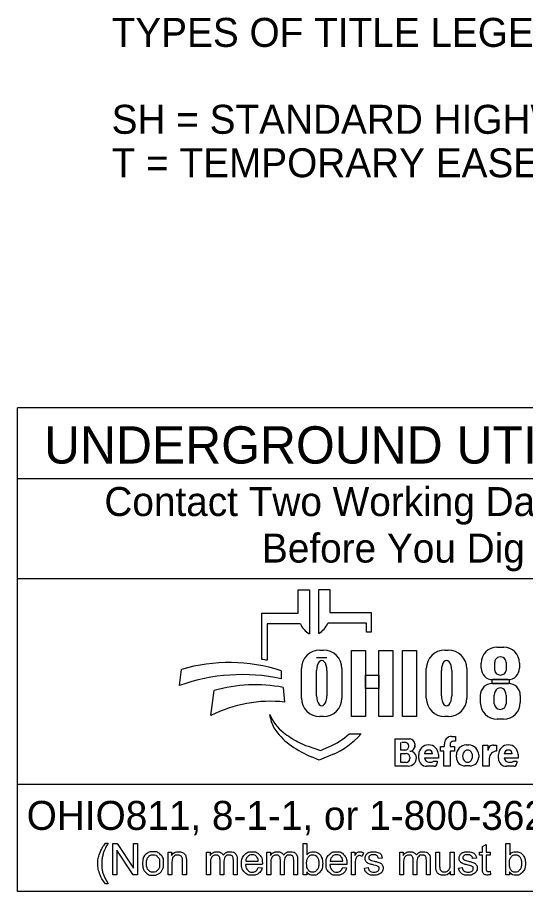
# Model space of a CAD drawing. Extents: x 0 to 34, y 0 to 22.
# Drawn here: x 18.411 to 20.865, y 5.128 to 9.351 of the extents above; entities that cross this region are included whole.
import ezdxf

# ---------------------------------------------------------------- set-up
doc = ezdxf.new("R2010")
doc.units = 0
doc.layers.add('SH_Data', color=7, linetype='Continuous')
doc.layers.add('SH_Text', color=7, linetype='Continuous')

msp = doc.modelspace()

# ---------------------------------------------------------------- linework, layer by layer
at = {"layer": 'SH_Data'}
for p, q in [((18.4115, 5.1281), (18.4115, 7.4656)), ((22.6615, 7.4656), (18.4115, 7.4656)), ((18.4115, 7.124), (22.6615, 7.124)), ((18.4115, 6.6407), (22.6615, 6.6407)), ((22.6615, 5.646), (18.4115, 5.646)), ((22.6615, 5.1281), (18.4115, 5.1281))]:
    msp.add_line(p, q, dxfattribs=at)
at = {"layer": 'SH_Text'}
for p, q in [((19.7675, 6.4736), (19.7675, 6.5851)), ((19.7675, 6.5851), (19.8211, 6.5851)), ((19.8211, 6.5851), (19.8211, 6.373)), ((19.8668, 6.3754), (19.8668, 6.5874)), ((19.8668, 6.5874), (19.9205, 6.5874)), ((19.9205, 6.5874), (19.9205, 6.4759)), ((19.5915, 6.2497), (19.5915, 6.4736)), ((19.5915, 6.4736), (19.7675, 6.4736)), ((19.9205, 6.4759), (20.1197, 6.4759)), ((20.1197, 6.4759), (20.1197, 6.3821)), ((19.6168, 6.4222), (19.6168, 6.2453)), ((19.7779, 6.4222), (19.6168, 6.4222)), ((20.0964, 6.4245), (19.91, 6.4245)), ((20.0964, 6.3821), (20.0964, 6.4245)), ((20.1197, 6.3821), (20.0964, 6.3821)), ((19.8725, 6.2944), (19.889, 6.2944)), ((20.4755, 6.2944), (20.4921, 6.2944)), ((20.7271, 6.3084), (20.7598, 6.3084)), ((19.9058, 6.2574), (19.856, 6.2574)), ((20.6508, 6.2078), (20.6508, 6.2321)), ((20.7169, 6.1964), (20.7169, 6.2357)), ((20.7711, 6.2357), (20.7711, 6.1964)), ((20.8361, 6.2321), (20.8361, 6.2078)), ((19.1942, 6.1234), (19.2036, 6.2016)), ((19.6849, 6.1951), (19.6849, 6.1562)), ((19.783, 6.063), (19.783, 6.205)), ((19.8559, 6.0743), (19.8559, 6.1967)), ((19.9057, 6.1967), (19.9057, 6.0743)), ((19.9785, 6.205), (19.9785, 6.063)), ((20.3861, 6.063), (20.3861, 6.205)), ((20.459, 6.0743), (20.459, 6.1967)), ((20.5088, 6.1967), (20.5088, 6.0743)), ((20.5815, 6.205), (20.5815, 6.063)), ((20.7049, 6.1335), (20.7823, 6.1335)), ((20.7801, 6.1518), (20.7068, 6.1518)), ((19.346, 5.9789), (19.3607, 6.099)), ((19.6948, 6.1145), (19.701, 6.0435)), ((20.6471, 6.0416), (20.6471, 6.0756)), ((20.7146, 6.0356), (20.7146, 6.0766)), ((20.7714, 6.0766), (20.7714, 6.0356)), ((20.8402, 6.0756), (20.8402, 6.0416)), ((19.6337, 5.966), (19.6306, 5.9839)), ((19.889, 5.9735), (19.8725, 5.9735)), ((20.4921, 5.9735), (20.4755, 5.9735)), ((20.7592, 5.9607), (20.728, 5.9607)), ((20.014, 5.8901), (20.0714, 5.8901)), ((20.5079, 5.8779), (20.5273, 5.8779)), ((20.5273, 5.8779), (20.5273, 5.8549)), ((19.8156, 5.8297), (19.875, 5.8093)), ((20.2353, 5.7344), (20.2353, 5.8651)), ((20.2353, 5.8651), (20.3065, 5.8651)), ((20.2633, 5.8116), (20.2633, 5.8485)), ((20.2885, 5.8485), (20.2672, 5.8485)), ((20.3302, 5.8413), (20.3302, 5.8334)), ((20.4553, 5.8065), (20.4553, 5.8295)), ((20.4553, 5.8295), (20.4746, 5.8295)), ((20.4746, 5.8295), (20.4746, 5.84)), ((20.5007, 5.8379), (20.5007, 5.8295)), ((20.5007, 5.8295), (20.5222, 5.8295)), ((20.5273, 5.8544), (20.5172, 5.8544)), ((20.5222, 5.8295), (20.5222, 5.8065)), ((20.5791, 5.8361), (20.5912, 5.8361)), ((20.6593, 5.7332), (20.6593, 5.8359)), ((20.6593, 5.8359), (20.6839, 5.8359)), ((20.6839, 5.8359), (20.6839, 5.809)), ((20.7111, 5.8359), (20.725, 5.8359)), ((20.725, 5.8359), (20.725, 5.8062)), ((19.9322, 5.7897), (19.869, 5.7622)), ((19.875, 5.8093), (19.916, 5.8271)), ((20.2827, 5.8116), (20.2633, 5.8116)), ((20.2633, 5.7522), (20.2633, 5.7951)), ((20.2633, 5.7951), (20.2888, 5.7951)), ((20.3498, 5.7711), (20.3498, 5.7896)), ((20.4164, 5.7935), (20.3779, 5.7935)), ((20.4444, 5.7896), (20.4444, 5.7719)), ((20.4702, 5.8065), (20.4553, 5.8065)), ((20.4702, 5.7332), (20.4702, 5.8065)), ((20.5222, 5.8065), (20.5007, 5.8065)), ((20.5007, 5.8065), (20.5007, 5.7332)), ((20.5313, 5.7775), (20.5313, 5.7883)), ((20.639, 5.7883), (20.639, 5.7775)), ((20.7348, 5.7711), (20.7348, 5.7896)), ((20.8013, 5.7935), (20.7628, 5.7935)), ((20.8293, 5.7896), (20.8293, 5.7719)), ((19.869, 5.7622), (19.8316, 5.7787)), ((20.2885, 5.7522), (20.2633, 5.7522)), ((20.3069, 5.7769), (20.3069, 5.7706)), ((20.3383, 5.774), (20.3383, 5.7737)), ((20.4444, 5.7719), (20.3779, 5.7719)), ((20.3989, 5.7526), (20.413, 5.7526)), ((20.4216, 5.7582), (20.4384, 5.7582)), ((20.4384, 5.7582), (20.4384, 5.7484)), ((20.6899, 5.7713), (20.6899, 5.7332)), ((20.8293, 5.7719), (20.7629, 5.7719)), ((20.7838, 5.7526), (20.7979, 5.7526)), ((20.8065, 5.7582), (20.8233, 5.7582)), ((20.8233, 5.7582), (20.8233, 5.7484)), ((20.2989, 5.7344), (20.2353, 5.7344)), ((20.4232, 5.7332), (20.3878, 5.7332)), ((20.5007, 5.7332), (20.4702, 5.7332)), ((20.5963, 5.7347), (20.5741, 5.7347)), ((20.6899, 5.7332), (20.6593, 5.7332)), ((20.8081, 5.7332), (20.7727, 5.7332))]:
    msp.add_line(p, q, dxfattribs=at)
for points in [[(20.0249, 6.2934), (20.0929, 6.2934), (20.0929, 5.9734), (20.0249, 5.9734)], [(20.1571, 6.2934), (20.225, 6.2934), (20.225, 5.9734), (20.1571, 5.9734)], [(20.2704, 6.2934), (20.3392, 6.2934), (20.3392, 5.9734), (20.2704, 5.9734)], [(20.0929, 6.1735), (20.1571, 6.1735), (20.1571, 6.1095), (20.0929, 6.1095)], [(20.7046, 6.1519), (20.7863, 6.1519), (20.7863, 6.1334), (20.7046, 6.1334)]]:
    msp.add_lwpolyline(points, close=True, dxfattribs=at)
for points in [[(18.8361, 5.3619), (18.8493, 5.3619)], [(18.8728, 5.2092), (18.8728, 5.3594), (18.8932, 5.3594), (18.9722, 5.2415), (18.9722, 5.3594), (18.9912, 5.3594), (18.9912, 5.2092), (18.9708, 5.2092), (18.8918, 5.3272), (18.8918, 5.2092), (18.8728, 5.2092)], [(19.8083, 5.2092), (19.7912, 5.2092), (19.7912, 5.3594), (19.8097, 5.3594), (19.8097, 5.3059)], [(20.6572, 5.2411), (20.6572, 5.3038), (20.6436, 5.3038), (20.6436, 5.3181), (20.6572, 5.3181), (20.6572, 5.345), (20.6757, 5.3561), (20.6757, 5.3181), (20.6941, 5.3181), (20.6941, 5.3038), (20.6757, 5.3038), (20.6757, 5.24)], [(20.7874, 5.2092), (20.7703, 5.2092), (20.7703, 5.3594), (20.7887, 5.3594), (20.7887, 5.3059)], [(19.1388, 5.2092), (19.1388, 5.3181), (19.1554, 5.3181), (19.1554, 5.3026)], [(19.3252, 5.2092), (19.3252, 5.3181), (19.3417, 5.3181), (19.3417, 5.3027)], [(19.4083, 5.2724), (19.4083, 5.2092), (19.3899, 5.2092), (19.3899, 5.2799)], [(19.4727, 5.2839), (19.4727, 5.2092), (19.4543, 5.2092), (19.4543, 5.2777)], [(19.6166, 5.2092), (19.6166, 5.3181), (19.6331, 5.3181), (19.6331, 5.3027)], [(19.6997, 5.2724), (19.6997, 5.2092), (19.6812, 5.2092), (19.6812, 5.2799)], [(19.7641, 5.2839), (19.7641, 5.2092), (19.7457, 5.2092), (19.7457, 5.2777)], [(20.0244, 5.2092), (20.0244, 5.3181), (20.041, 5.3181), (20.041, 5.3016)], [(20.0834, 5.3146), (20.077, 5.2975)], [(20.1734, 5.2899), (20.1553, 5.2875)], [(20.2576, 5.2092), (20.2576, 5.3181), (20.2741, 5.3181), (20.2741, 5.3027)], [(20.3407, 5.2724), (20.3407, 5.2092), (20.3222, 5.2092), (20.3222, 5.2799)], [(20.4051, 5.2839), (20.4051, 5.2092), (20.3867, 5.2092), (20.3867, 5.2777)], [(20.4319, 5.2507), (20.4319, 5.3181), (20.4503, 5.3181), (20.4503, 5.2578)], [(20.5016, 5.2598), (20.5016, 5.3181), (20.52, 5.3181), (20.52, 5.2092), (20.5035, 5.2092)], [(20.6279, 5.2899), (20.6099, 5.2875)], [(19.1572, 5.2686), (19.1572, 5.2092), (19.1388, 5.2092)], [(19.2272, 5.2761), (19.2272, 5.2092), (19.2087, 5.2092), (19.2087, 5.2754)], [(19.3436, 5.2657), (19.3436, 5.2092), (19.3252, 5.2092)], [(19.594, 5.2589), (19.5128, 5.2589)], [(19.5138, 5.274), (19.5746, 5.274)], [(19.5744, 5.2444), (19.5934, 5.242)], [(19.635, 5.2657), (19.635, 5.2092), (19.6166, 5.2092)], [(20.002, 5.2589), (19.9208, 5.2589)], [(19.9218, 5.274), (19.9826, 5.274)], [(19.9824, 5.2444), (20.0014, 5.242)], [(20.0428, 5.2662), (20.0428, 5.2092), (20.0244, 5.2092)], [(20.087, 5.2417), (20.1052, 5.2446)], [(20.276, 5.2657), (20.276, 5.2092), (20.2576, 5.2092)], [(20.5415, 5.2417), (20.5597, 5.2446)], [(19.8083, 5.2229), (19.8083, 5.2092)], [(20.5035, 5.2092), (20.5035, 5.2253)], [(20.6941, 5.2257), (20.6967, 5.2094)], [(20.7874, 5.2229), (20.7874, 5.2092)], [(18.8493, 5.1651), (18.8361, 5.1651)]]:
    msp.add_lwpolyline(points, dxfattribs=at)
for centre, radius, start, end in [((19.8693, 6.4589), 0.0985, 201.9296, 240.7469), ((19.8187, 6.4613), 0.0985, 299.2531, 338.0704), ((19.8725, 6.205), 0.0895, 90, 180), ((19.889, 6.205), 0.0895, 0, 90), ((20.4755, 6.205), 0.0895, 90, 180), ((20.4921, 6.205), 0.0895, 0, 90), ((20.7271, 6.2321), 0.0763, 90, 180), ((20.7598, 6.2321), 0.0763, 0, 90), ((19.4337, 5.4155), 0.8191, 72.1402, 106.3144), ((19.4634, 5.4408), 0.8191, 79.2074, 81.0007), ((19.4967, 5.2844), 0.8919, 77.8238, 109.8274), ((20.7068, 6.2078), 0.056, 180, 270), ((20.7801, 6.2078), 0.056, 270, 0), ((19.5606, 5.3947), 0.7322, 79.44, 105.8467), ((20.7049, 6.0756), 0.0579, 90, 180), ((20.7823, 6.0756), 0.0579, 0, 90), ((19.6327, 5.4115), 0.6357, 83.8248, 116.8021), ((19.8725, 6.063), 0.0895, 180, 270), ((19.889, 6.063), 0.0895, 270, 0), ((20.4755, 6.063), 0.0895, 180, 270), ((20.4921, 6.063), 0.0895, 270, 0), ((20.728, 6.0416), 0.081, 180, 270), ((20.7592, 6.0416), 0.081, 270, 0), ((19.818, 6.056), 0.2008, 201.0457, 232.5314), ((19.775, 5.9901), 0.1433, 189.6817, 216.0884), ((19.9087, 6.0875), 0.3088, 216.0884, 235.7167), ((20.0106, 6.3072), 0.5173, 232.5314, 241.794), ((19.7726, 6.1575), 0.3602, 293.4582, 312.0712), ((19.7726, 6.1575), 0.401, 293.4582, 317.8286), ((20.5079, 5.8443), 0.0335, 90, 187.5187), ((20.0752, 6.3318), 0.6044, 235.7167, 246.2325), ((19.9254, 6.1484), 0.3371, 241.794, 250.9821), ((20.2827, 5.8303), 0.0187, 270, 2.0582), ((20.2845, 5.8317), 0.0169, 357.8325, 90), ((20.3061, 5.8306), 0.0243, 270, 6.6529), ((20.3065, 5.8413), 0.0238, 0, 90), ((20.3167, 5.8291), 0.0175, 347.4023, 0), ((20.3971, 5.7896), 0.0473, 0, 180), ((20.5172, 5.8379), 0.0165, 90, 180), ((20.5791, 5.7883), 0.0478, 90, 180), ((20.5912, 5.7883), 0.0478, 0, 90), ((20.7108, 5.809), 0.0269, 89.2449, 180), ((20.782, 5.7896), 0.0473, 0, 180), ((20.2888, 5.7769), 0.0181, 0, 90), ((20.3062, 5.7742), 0.0321, 4.0748, 90), ((20.3972, 5.7925), 0.0193, 2.9632, 177.0368), ((20.7248, 5.7713), 0.0349, 89.6033, 180), ((20.7821, 5.7925), 0.0193, 2.9632, 177.0368), ((20.2885, 5.7706), 0.0184, 270, 0), ((20.2989, 5.7737), 0.0393, 270, 0), ((20.3053, 5.774), 0.033, 0, 11.7502), ((20.3878, 5.7711), 0.038, 180, 270), ((20.3989, 5.7737), 0.021, 184.827, 270), ((20.413, 5.762), 0.00938, 270, 335.9979), ((20.4232, 5.7484), 0.0152, 270, 0), ((20.5741, 5.7775), 0.0428, 180, 270), ((20.5963, 5.7775), 0.0428, 270, 0), ((20.7727, 5.7711), 0.038, 180, 270), ((20.7838, 5.7737), 0.021, 184.827, 270), ((20.7979, 5.762), 0.00938, 270, 335.9979), ((20.8081, 5.7484), 0.0152, 270, 0)]:
    msp.add_arc(centre, radius, start, end, dxfattribs=at)
for centre, major_axis, ratio, start_param, end_param in [((20.744, 6.2357), (0.0271, 0), 0.969373, 0, 3.141593), ((19.8808, 6.1967), (0, 0.0484), 0.514403, 4.712389, 7.853982), ((20.4839, 6.1967), (0, 0.0484), 0.514403, 4.712389, 7.853982), ((20.744, 6.1964), (0.0271, 0), 0.818453, 3.141593, 6.283185), ((20.743, 6.0766), (0, 0.0358), 0.794529, 4.712389, 7.853982), ((19.8808, 6.0743), (0, 0.0484), 0.514403, 1.570796, 4.712389), ((20.4839, 6.0743), (0, 0.0484), 0.514403, 1.570796, 4.712389), ((20.743, 6.0356), (0.0284, 0), 0.959837, 3.141593, 6.283185), ((20.5856, 5.7829), (0, 0.029), 0.832186, 4.712389, 7.853982), ((20.5856, 5.7829), (0, 0.0302), 0.797287, 1.570796, 4.712389)]:
    msp.add_ellipse(centre, major_axis=major_axis, ratio=ratio, start_param=start_param, end_param=end_param, dxfattribs=at)
for points in [[(18.8361, 5.1651), (18.8208, 5.1843), (18.8103, 5.2101), (18.7997, 5.2359), (18.7997, 5.2636), (18.7997, 5.288), (18.8076, 5.3103), (18.8168, 5.3362), (18.8361, 5.3619)], [(18.8493, 5.3619), (18.8369, 5.3406), (18.8329, 5.3315), (18.8267, 5.3174), (18.8231, 5.302), (18.8187, 5.2829), (18.8187, 5.2635), (18.8187, 5.2142), (18.8493, 5.1651)], [(19.0153, 5.2637), (19.0153, 5.2939), (19.0321, 5.3084), (19.0461, 5.3205), (19.0663, 5.3205), (19.0887, 5.3205), (19.1029, 5.3058), (19.1172, 5.2911), (19.1172, 5.2652), (19.1172, 5.2442), (19.1109, 5.2322), (19.1046, 5.2202), (19.0926, 5.2135), (19.0805, 5.2068), (19.0663, 5.2068), (19.0435, 5.2068), (19.0294, 5.2215), (19.0153, 5.2361), (19.0153, 5.2637)], [(19.0343, 5.2637), (19.0343, 5.2428), (19.0434, 5.2324), (19.0525, 5.2219), (19.0663, 5.2219), (19.08, 5.2219), (19.0891, 5.2324), (19.0982, 5.2429), (19.0982, 5.2643), (19.0982, 5.2845), (19.089, 5.2949), (19.0799, 5.3053), (19.0663, 5.3053), (19.0525, 5.3053), (19.0434, 5.2949), (19.0343, 5.2846), (19.0343, 5.2637)], [(19.1554, 5.3026), (19.1674, 5.3205), (19.19, 5.3205), (19.1998, 5.3205), (19.2081, 5.317), (19.2163, 5.3134), (19.2204, 5.3077), (19.2245, 5.3019), (19.2261, 5.2941), (19.2272, 5.2889), (19.2272, 5.2761)], [(19.2087, 5.2754), (19.2087, 5.2866), (19.2066, 5.2922), (19.2044, 5.2978), (19.199, 5.3011), (19.1935, 5.3045), (19.1861, 5.3045), (19.1743, 5.3045), (19.1658, 5.297), (19.1572, 5.2895), (19.1572, 5.2686)], [(19.3417, 5.3027), (19.3468, 5.3107), (19.3553, 5.3156), (19.3638, 5.3205), (19.3747, 5.3205), (19.3868, 5.3205), (19.3945, 5.3155), (19.4023, 5.3104), (19.4054, 5.3014), (19.4184, 5.3205), (19.4391, 5.3205), (19.4553, 5.3205), (19.464, 5.3115), (19.4727, 5.3026), (19.4727, 5.2839)], [(19.3899, 5.2799), (19.3899, 5.2922), (19.3854, 5.2983), (19.3809, 5.3045), (19.3706, 5.3045), (19.3628, 5.3045), (19.3562, 5.3004), (19.3496, 5.2963), (19.3466, 5.2884), (19.3436, 5.2805), (19.3436, 5.2657)], [(19.4543, 5.2777), (19.4543, 5.2888), (19.4525, 5.2937), (19.4507, 5.2985), (19.446, 5.3015), (19.4413, 5.3045), (19.4349, 5.3045), (19.4235, 5.3045), (19.4159, 5.2968), (19.4083, 5.2892), (19.4083, 5.2724)], [(19.5934, 5.242), (19.5889, 5.2253), (19.5768, 5.2161), (19.5646, 5.2068), (19.5456, 5.2068), (19.5218, 5.2068), (19.5078, 5.2215), (19.4938, 5.2362), (19.4938, 5.2627), (19.4938, 5.2902), (19.5079, 5.3053), (19.5221, 5.3205), (19.5446, 5.3205), (19.5664, 5.3205), (19.5802, 5.3056), (19.5941, 5.2908), (19.5941, 5.2638), (19.5941, 5.2622), (19.594, 5.2589)], [(19.5746, 5.274), (19.5734, 5.2878), (19.5676, 5.2947), (19.5588, 5.3054), (19.5448, 5.3054), (19.5321, 5.3054), (19.5234, 5.2968), (19.5148, 5.2883), (19.5138, 5.274)], [(19.6331, 5.3027), (19.6382, 5.3107), (19.6467, 5.3156), (19.6552, 5.3205), (19.6661, 5.3205), (19.6782, 5.3205), (19.6859, 5.3155), (19.6936, 5.3104), (19.6968, 5.3014), (19.7097, 5.3205), (19.7305, 5.3205), (19.7467, 5.3205), (19.7554, 5.3115), (19.7641, 5.3026), (19.7641, 5.2839)], [(19.6812, 5.2799), (19.6812, 5.2922), (19.6767, 5.2983), (19.6722, 5.3045), (19.662, 5.3045), (19.6542, 5.3045), (19.6476, 5.3004), (19.641, 5.2963), (19.638, 5.2884), (19.635, 5.2805), (19.635, 5.2657)], [(19.7457, 5.2777), (19.7457, 5.2888), (19.7439, 5.2937), (19.7421, 5.2985), (19.7374, 5.3015), (19.7327, 5.3045), (19.7263, 5.3045), (19.7148, 5.3045), (19.7073, 5.2968), (19.6997, 5.2892), (19.6997, 5.2724)], [(19.8081, 5.2645), (19.8081, 5.2449), (19.8134, 5.2362), (19.8221, 5.2219), (19.8369, 5.2219), (19.849, 5.2219), (19.8578, 5.2325), (19.8666, 5.243), (19.8666, 5.2638), (19.8666, 5.2851), (19.8581, 5.2952), (19.8497, 5.3054), (19.8377, 5.3054), (19.8257, 5.3054), (19.8169, 5.2949), (19.8081, 5.2844), (19.8081, 5.2645)], [(19.8097, 5.3059), (19.8213, 5.3205), (19.8395, 5.3205), (19.8495, 5.3205), (19.8585, 5.3164), (19.8674, 5.3124), (19.8732, 5.3051), (19.879, 5.2978), (19.8823, 5.2874), (19.8855, 5.2771), (19.8855, 5.2653), (19.8855, 5.2374), (19.8717, 5.2221), (19.8579, 5.2068), (19.8385, 5.2068), (19.8193, 5.2068), (19.8083, 5.2229)], [(20.0014, 5.242), (19.9969, 5.2253), (19.9847, 5.2161), (19.9726, 5.2068), (19.9536, 5.2068), (19.9298, 5.2068), (19.9158, 5.2215), (19.9018, 5.2362), (19.9018, 5.2627), (19.9018, 5.2902), (19.9159, 5.3053), (19.9301, 5.3205), (19.9526, 5.3205), (19.9744, 5.3205), (19.9882, 5.3056), (20.0021, 5.2908), (20.0021, 5.2638), (20.0021, 5.2622), (20.002, 5.2589)], [(19.9826, 5.274), (19.9814, 5.2878), (19.9756, 5.2947), (19.9668, 5.3054), (19.9528, 5.3054), (19.9401, 5.3054), (19.9314, 5.2968), (19.9228, 5.2883), (19.9218, 5.274)], [(20.041, 5.3016), (20.0473, 5.3131), (20.0527, 5.3168), (20.0581, 5.3205), (20.0645, 5.3205), (20.0738, 5.3205), (20.0834, 5.3146)], [(20.077, 5.2975), (20.0702, 5.3015), (20.0635, 5.3015), (20.0575, 5.3015), (20.0527, 5.2979), (20.0479, 5.2942), (20.0459, 5.2878), (20.0428, 5.2779), (20.0428, 5.2662)], [(20.1553, 5.2875), (20.1541, 5.2959), (20.1482, 5.3007), (20.1423, 5.3054), (20.1315, 5.3054), (20.1188, 5.3054), (20.1133, 5.3012), (20.1079, 5.297), (20.1079, 5.2913), (20.1079, 5.2877), (20.1102, 5.2849), (20.1124, 5.2819), (20.1172, 5.2799), (20.12, 5.2789), (20.1336, 5.2752), (20.1531, 5.27), (20.1609, 5.2667), (20.1687, 5.2633), (20.1731, 5.257), (20.1775, 5.2506), (20.1775, 5.2412), (20.1775, 5.232), (20.1721, 5.2239), (20.1667, 5.2157), (20.1566, 5.2113), (20.1464, 5.2068), (20.1336, 5.2068), (20.1123, 5.2068), (20.1012, 5.2156), (20.09, 5.2244), (20.087, 5.2417)], [(20.1052, 5.2446), (20.1067, 5.2336), (20.1137, 5.2278), (20.1208, 5.2219), (20.1334, 5.2219), (20.1462, 5.2219), (20.1523, 5.2271), (20.1585, 5.2323), (20.1585, 5.2393), (20.1585, 5.2455), (20.153, 5.2491), (20.1492, 5.2516), (20.1342, 5.2554), (20.1139, 5.2605), (20.106, 5.2642), (20.0982, 5.268), (20.0941, 5.2746), (20.0901, 5.2812), (20.0901, 5.2892), (20.0901, 5.2964), (20.0934, 5.3026), (20.0967, 5.3088), (20.1025, 5.3129), (20.1068, 5.3161), (20.1142, 5.3183), (20.1217, 5.3205), (20.1302, 5.3205), (20.143, 5.3205), (20.1527, 5.3168), (20.1624, 5.3131), (20.167, 5.3068), (20.1716, 5.3005), (20.1734, 5.2899)], [(20.2741, 5.3027), (20.2792, 5.3107), (20.2877, 5.3156), (20.2962, 5.3205), (20.3071, 5.3205), (20.3192, 5.3205), (20.3269, 5.3155), (20.3346, 5.3104), (20.3378, 5.3014), (20.3507, 5.3205), (20.3715, 5.3205), (20.3877, 5.3205), (20.3964, 5.3115), (20.4051, 5.3026), (20.4051, 5.2839)], [(20.3222, 5.2799), (20.3222, 5.2922), (20.3177, 5.2983), (20.3132, 5.3045), (20.303, 5.3045), (20.2952, 5.3045), (20.2886, 5.3004), (20.282, 5.2963), (20.279, 5.2884), (20.276, 5.2805), (20.276, 5.2657)], [(20.3867, 5.2777), (20.3867, 5.2888), (20.3849, 5.2937), (20.3831, 5.2985), (20.3784, 5.3015), (20.3737, 5.3045), (20.3673, 5.3045), (20.3558, 5.3045), (20.3483, 5.2968), (20.3407, 5.2892), (20.3407, 5.2724)], [(20.6099, 5.2875), (20.6086, 5.2959), (20.6027, 5.3007), (20.5968, 5.3054), (20.5861, 5.3054), (20.5734, 5.3054), (20.5679, 5.3012), (20.5625, 5.297), (20.5625, 5.2913), (20.5625, 5.2877), (20.5647, 5.2849), (20.567, 5.2819), (20.5718, 5.2799), (20.5746, 5.2789), (20.5881, 5.2752), (20.6077, 5.27), (20.6155, 5.2667), (20.6232, 5.2633), (20.6276, 5.257), (20.6321, 5.2506), (20.6321, 5.2412), (20.6321, 5.232), (20.6267, 5.2239), (20.6213, 5.2157), (20.6111, 5.2113), (20.601, 5.2068), (20.5881, 5.2068), (20.5669, 5.2068), (20.5558, 5.2156), (20.5446, 5.2244), (20.5415, 5.2417)], [(20.5597, 5.2446), (20.5613, 5.2336), (20.5683, 5.2278), (20.5754, 5.2219), (20.588, 5.2219), (20.6007, 5.2219), (20.6069, 5.2271), (20.6131, 5.2323), (20.6131, 5.2393), (20.6131, 5.2455), (20.6076, 5.2491), (20.6038, 5.2516), (20.5887, 5.2554), (20.5684, 5.2605), (20.5606, 5.2642), (20.5527, 5.268), (20.5487, 5.2746), (20.5446, 5.2812), (20.5446, 5.2892), (20.5446, 5.2964), (20.548, 5.3026), (20.5513, 5.3088), (20.557, 5.3129), (20.5614, 5.3161), (20.5688, 5.3183), (20.5762, 5.3205), (20.5847, 5.3205), (20.5976, 5.3205), (20.6073, 5.3168), (20.617, 5.3131), (20.6216, 5.3068), (20.6262, 5.3005), (20.6279, 5.2899)], [(20.7871, 5.2645), (20.7871, 5.2449), (20.7925, 5.2362), (20.8011, 5.2219), (20.816, 5.2219), (20.828, 5.2219), (20.8368, 5.2325), (20.8456, 5.243), (20.8456, 5.2638), (20.8456, 5.2851), (20.8372, 5.2952), (20.8287, 5.3054), (20.8168, 5.3054), (20.8047, 5.3054), (20.7959, 5.2949), (20.7871, 5.2844), (20.7871, 5.2645)], [(20.7887, 5.3059), (20.8004, 5.3205), (20.8185, 5.3205), (20.8286, 5.3205), (20.8375, 5.3164), (20.8465, 5.3124), (20.8523, 5.3051), (20.8581, 5.2978), (20.8613, 5.2874), (20.8646, 5.2771), (20.8646, 5.2653), (20.8646, 5.2374), (20.8508, 5.2221), (20.837, 5.2068), (20.8176, 5.2068), (20.7983, 5.2068), (20.7874, 5.2229)], [(19.5128, 5.2589), (19.5138, 5.241), (19.523, 5.2315), (19.5321, 5.2219), (19.5457, 5.2219), (19.5559, 5.2219), (19.563, 5.2273), (19.5702, 5.2327), (19.5744, 5.2444)], [(19.9208, 5.2589), (19.9218, 5.241), (19.9309, 5.2315), (19.9401, 5.2219), (19.9537, 5.2219), (19.9638, 5.2219), (19.971, 5.2273), (19.9782, 5.2327), (19.9824, 5.2444)], [(20.5035, 5.2253), (20.4909, 5.2068), (20.4691, 5.2068), (20.4594, 5.2068), (20.4511, 5.2105), (20.4428, 5.2142), (20.4387, 5.2198), (20.4347, 5.2254), (20.433, 5.2335), (20.4319, 5.2389), (20.4319, 5.2507)], [(20.4503, 5.2578), (20.4503, 5.2433), (20.4515, 5.2383), (20.4532, 5.231), (20.4588, 5.2269), (20.4645, 5.2228), (20.4727, 5.2228), (20.481, 5.2228), (20.4883, 5.227), (20.4956, 5.2313), (20.4986, 5.2386), (20.5016, 5.2459), (20.5016, 5.2598)], [(20.6967, 5.2094), (20.689, 5.2078), (20.6828, 5.2078), (20.6728, 5.2078), (20.6673, 5.2109), (20.6617, 5.2141), (20.6595, 5.2193), (20.6572, 5.2245), (20.6572, 5.2411)], [(20.6757, 5.24), (20.6757, 5.2321), (20.6766, 5.2299), (20.6776, 5.2276), (20.6798, 5.2263), (20.682, 5.2249), (20.6861, 5.2249), (20.6891, 5.2249), (20.6941, 5.2257)]]:
    msp.add_open_spline(points, degree=3, dxfattribs=at)

# ---------------------------------------------------------------- texts
for s, height, p in [('TYPES OF TITLE LEGEND:', 0.14, (18.8662, 9.2094)), ('SH = STANDARD HIGHWAY EASEMENT', 0.14, (18.8662, 8.7894)), ('T = TEMPORARY EASEMENT', 0.14, (18.8662, 8.5794)), ('UNDERGROUND UTILITIES', 0.18, (18.5396, 7.196)), ('Contact Two Working Days', 0.14, (18.8311, 6.9425)), ('Before You Dig', 0.14, (19.5923, 6.7175)), ('OHIO811, 8-1-1, or 1-800-362-2764', 0.14, (18.4559, 5.4259))]:
    msp.add_text(s, height=height, dxfattribs=at).set_placement(p)

doc.saveas('drawing.dxf')
